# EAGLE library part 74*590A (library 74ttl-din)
8-bit BINARY COUNTER with output register
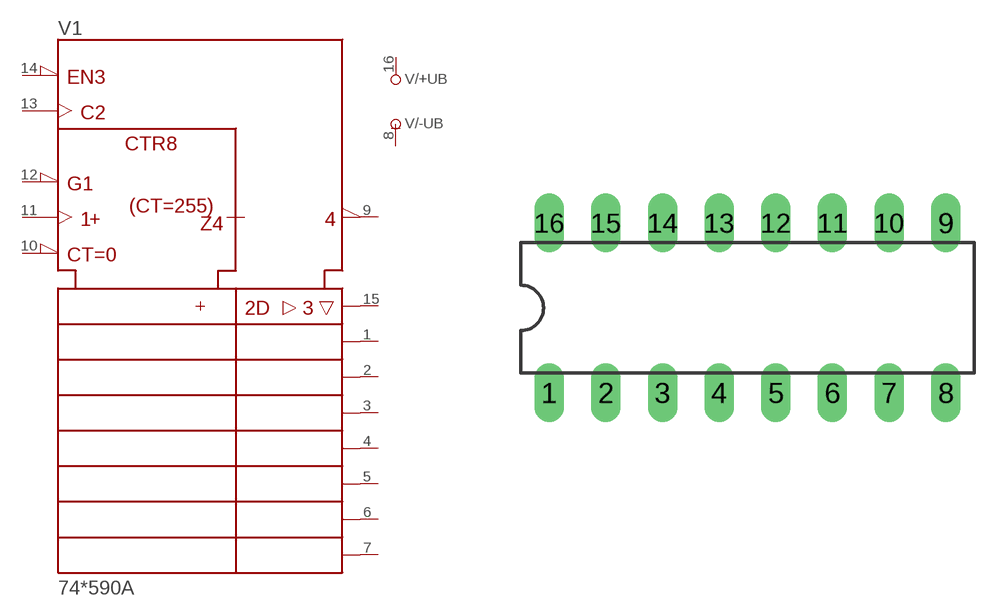
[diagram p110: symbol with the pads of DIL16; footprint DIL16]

Designator prefix V; gates /+UB=+UB /-UB=-UB 1=590A

## 74590AN  [DIL16]
1  1:QB  hiz
2  1:QC  hiz
3  1:QD  hiz
4  1:QE  hiz
5  1:QF  hiz
6  1:QG  hiz
7  1:QH  hiz
8  /-UB:-UB  pwr
9  1:RCO\  out
10  1:CCLR\  in
11  1:CCK  in
12  1:CCKEN\  in
13  1:RCK  in
14  1:G\  in
15  1:QA  hiz
16  /+UB:+UB  pwr

## Footprint DIL16 (pad centres in mm)
Dual In Line Package
drill 0.813 long: 1 -8.89,-3.81; 2 -6.35,-3.81; 3 -3.81,-3.81; 4 -1.27,-3.81; 5 1.27,-3.81; 6 3.81,-3.81; 7 6.35,-3.81; 8 8.89,-3.81; 9 8.89,3.81; 10 6.35,3.81; 11 3.81,3.81; 12 1.27,3.81; 13 -1.27,3.81; 14 -3.81,3.81; 15 -6.35,3.81; 16 -8.89,3.81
